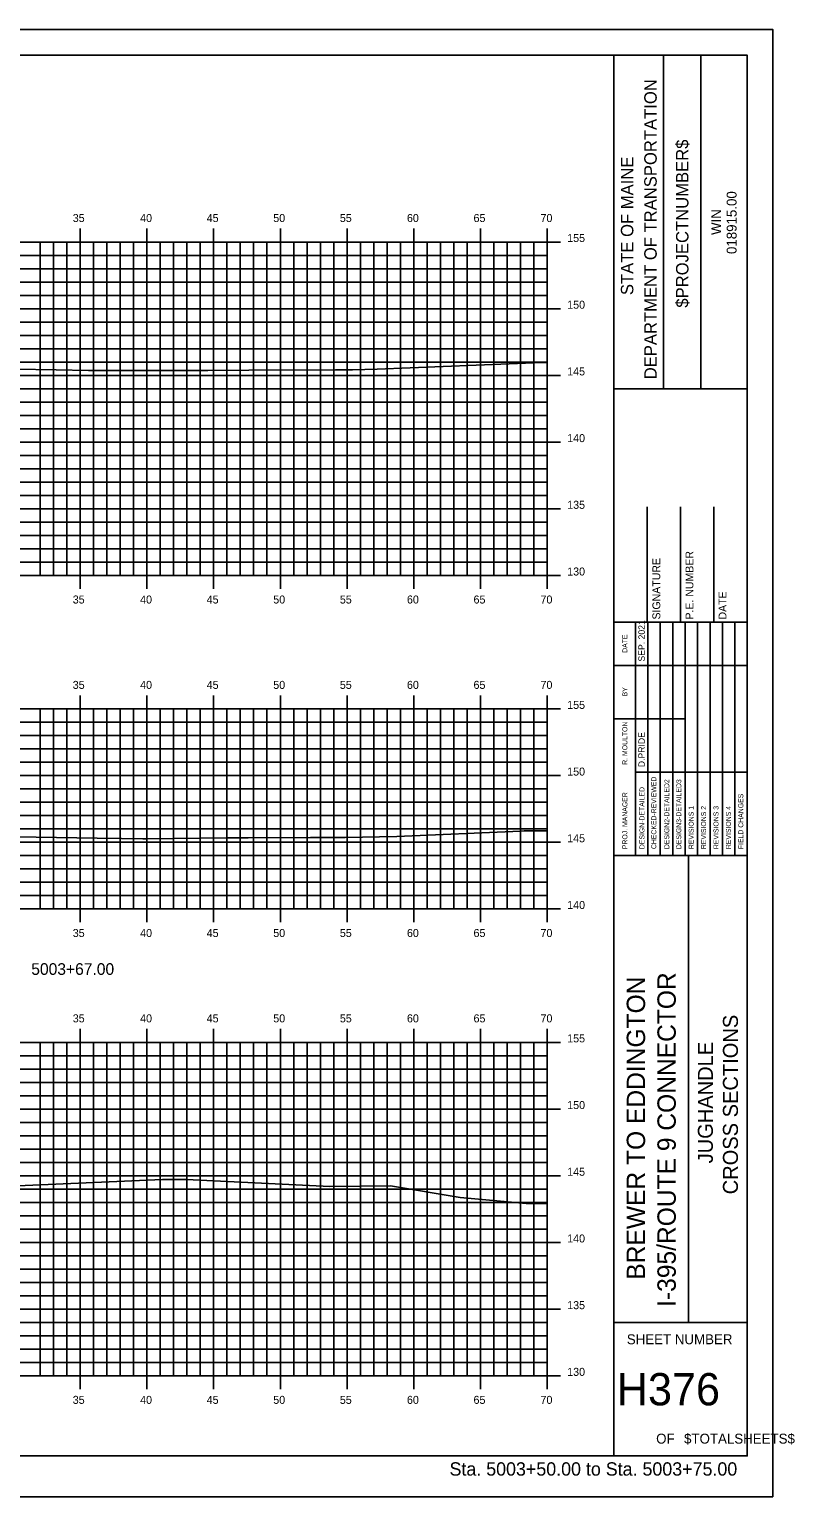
# Model space of a CAD drawing. Extents: x 851860 to 852032, y 365876 to 365986.
# Drawn here: x 851974.6 to 852032, y 365875.8 to 365985.8 of the extents above; entities that cross this region are included whole.
import ezdxf

# ---------------------------------------------------------------- set-up
doc = ezdxf.new("R2010")
doc.units = 0
for name, color, linetype in [('BORDER', 7, 'Continuous'), ('H_V ANNOTATION', 7, 'Continuous'), ('MAJOR', 7, 'Continuous'), ('MINOR', 7, 'Continuous'), ('PLOT BOUNDARY', 7, 'Continuous'), ('S_Roadway_Centerline', 7, 'Continuous')]:
    doc.layers.add(name, color=color, linetype=linetype)

msp = doc.modelspace()

# ---------------------------------------------------------------- linework, layer by layer
at = {"layer": 'BORDER'}
for p, q in [((852018.41, 365878.83), (852018.41, 365983.83)), ((852022.14, 365958.83), (852022.14, 365983.83)), ((852024.94, 365958.83), (852024.94, 365983.83)), ((852018.41, 365958.83), (852028.41, 365958.83)), ((852020.91, 365941.34), (852020.91, 365949.98)), ((852023.41, 365941.34), (852023.41, 365949.98)), ((852025.91, 365941.34), (852025.91, 365949.98)), ((852018.41, 365941.34), (852028.41, 365941.34)), ((852018.41, 365923.84), (852028.41, 365923.84)), ((852024, 365888.84), (852024, 365923.84)), ((852018.41, 365888.84), (852028.41, 365888.84))]:
    msp.add_line(p, q, dxfattribs=at)
msp.add_lwpolyline([(851868.41, 365878.83), (852028.41, 365878.83), (852028.41, 365983.83), (851868.41, 365983.83)], close=True, dxfattribs=at)
for points in [[(852020.03, 365938.09), (852020.03, 365941.34)], [(852020.03, 365923.84), (852020.03, 365940.63)], [(852020.96, 365923.84), (852020.96, 365941.34)], [(852021.89, 365941.34), (852021.89, 365923.84)], [(852022.82, 365923.84), (852022.82, 365941.34)], [(852023.75, 365923.84), (852023.75, 365941.34)], [(852024.69, 365923.84), (852024.69, 365941.34)], [(852025.62, 365923.84), (852025.62, 365941.34)], [(852026.55, 365923.84), (852026.55, 365941.34)], [(852027.48, 365923.84), (852027.48, 365941.34)], [(852018.41, 365938.09), (852028.41, 365938.09)], [(852018.41, 365934.09), (852020.03, 365934.09)], [(852020.03, 365934.09), (852023.75, 365934.09)], [(852020.03, 365930.09), (852028.41, 365930.09)]]:
    msp.add_lwpolyline(points, dxfattribs=at)
at = {"layer": 'MAJOR'}
for p, q in [((851978.41, 365970.84), (851978.41, 365969.83)), ((851983.41, 365970.84), (851983.41, 365969.83)), ((851988.41, 365970.84), (851988.41, 365969.83)), ((851993.41, 365970.84), (851993.41, 365969.83)), ((851998.41, 365970.84), (851998.41, 365969.83)), ((852003.41, 365970.84), (852003.41, 365969.83)), ((852008.41, 365970.84), (852008.41, 365969.83)), ((852013.41, 365970.84), (852013.41, 365969.83)), ((851873.41, 365969.83), (852013.41, 365969.83)), ((851873.41, 365969.83), (852013.41, 365969.83)), ((851978.41, 365944.83), (851978.41, 365969.83)), ((851983.41, 365944.83), (851983.41, 365969.83)), ((851988.41, 365944.83), (851988.41, 365969.83)), ((851993.41, 365944.83), (851993.41, 365969.83)), ((851998.41, 365944.83), (851998.41, 365969.83)), ((852003.41, 365944.83), (852003.41, 365969.83)), ((852008.41, 365944.83), (852008.41, 365969.83)), ((852014.41, 365969.83), (852012.41, 365969.83)), ((852013.41, 365944.83), (852013.41, 365969.83)), ((852013.41, 365944.83), (852013.41, 365969.83)), ((851873.41, 365964.83), (852013.41, 365964.83)), ((852014.41, 365964.83), (852012.41, 365964.83)), ((851873.41, 365959.83), (852013.41, 365959.83)), ((852014.41, 365959.83), (852012.41, 365959.83)), ((851873.41, 365954.83), (852013.41, 365954.83)), ((852014.41, 365954.83), (852012.41, 365954.83)), ((851873.41, 365949.83), (852013.41, 365949.83)), ((852014.41, 365949.83), (852012.41, 365949.83)), ((851873.41, 365944.83), (852013.41, 365944.83)), ((851873.41, 365944.83), (852013.41, 365944.83)), ((851978.41, 365943.83), (851978.41, 365944.83)), ((851983.41, 365943.83), (851983.41, 365944.83)), ((851988.41, 365943.83), (851988.41, 365944.83)), ((851993.41, 365943.83), (851993.41, 365944.83)), ((851998.41, 365943.83), (851998.41, 365944.83)), ((852003.41, 365943.83), (852003.41, 365944.83)), ((852008.41, 365943.83), (852008.41, 365944.83)), ((852014.41, 365944.83), (852012.41, 365944.83)), ((852013.41, 365943.83), (852013.41, 365944.83)), ((851943.41, 365934.83), (852013.41, 365934.83)), ((851943.41, 365934.83), (852013.41, 365934.83)), ((851978.41, 365935.84), (851978.41, 365934.83)), ((851978.41, 365919.83), (851978.41, 365934.83)), ((851983.41, 365935.84), (851983.41, 365934.83)), ((851983.41, 365919.83), (851983.41, 365934.83)), ((851988.41, 365935.84), (851988.41, 365934.83)), ((851988.41, 365919.83), (851988.41, 365934.83)), ((851993.41, 365935.84), (851993.41, 365934.83)), ((851993.41, 365919.83), (851993.41, 365934.83)), ((851998.41, 365935.84), (851998.41, 365934.83)), ((851998.41, 365919.83), (851998.41, 365934.83)), ((852003.41, 365935.84), (852003.41, 365934.83)), ((852003.41, 365919.83), (852003.41, 365934.83)), ((852008.41, 365935.84), (852008.41, 365934.83)), ((852008.41, 365919.83), (852008.41, 365934.83)), ((852014.41, 365934.83), (852012.41, 365934.83)), ((852013.41, 365935.84), (852013.41, 365934.83)), ((852013.41, 365919.83), (852013.41, 365934.83)), ((852013.41, 365919.83), (852013.41, 365934.83)), ((851943.41, 365929.83), (852013.41, 365929.83)), ((852014.41, 365929.83), (852012.41, 365929.83)), ((851943.41, 365924.83), (852013.41, 365924.83)), ((852014.41, 365924.83), (852012.41, 365924.83)), ((851943.41, 365919.83), (852013.41, 365919.83)), ((851943.41, 365919.83), (852013.41, 365919.83)), ((851978.41, 365918.83), (851978.41, 365919.83)), ((851983.41, 365918.83), (851983.41, 365919.83)), ((851988.41, 365918.83), (851988.41, 365919.83)), ((851993.41, 365918.83), (851993.41, 365919.83)), ((851998.41, 365918.83), (851998.41, 365919.83)), ((852003.41, 365918.83), (852003.41, 365919.83)), ((852008.41, 365918.83), (852008.41, 365919.83)), ((852014.41, 365919.83), (852012.41, 365919.83)), ((852013.41, 365918.83), (852013.41, 365919.83)), ((851978.41, 365910.84), (851978.41, 365909.83)), ((851983.41, 365910.84), (851983.41, 365909.83)), ((851988.41, 365910.84), (851988.41, 365909.83)), ((851993.41, 365910.84), (851993.41, 365909.83)), ((851998.41, 365910.84), (851998.41, 365909.83)), ((852003.41, 365910.84), (852003.41, 365909.83)), ((852008.41, 365910.84), (852008.41, 365909.83)), ((852013.41, 365910.84), (852013.41, 365909.83)), ((851873.41, 365909.83), (852013.41, 365909.83)), ((851873.41, 365909.83), (852013.41, 365909.83)), ((851978.41, 365884.83), (851978.41, 365909.83)), ((851983.41, 365884.83), (851983.41, 365909.83)), ((851988.41, 365884.83), (851988.41, 365909.83)), ((851993.41, 365884.83), (851993.41, 365909.83)), ((851998.41, 365884.83), (851998.41, 365909.83)), ((852003.41, 365884.83), (852003.41, 365909.83)), ((852008.41, 365884.83), (852008.41, 365909.83)), ((852014.41, 365909.83), (852012.41, 365909.83)), ((852013.41, 365884.83), (852013.41, 365909.83)), ((852013.41, 365884.83), (852013.41, 365909.83)), ((851873.41, 365904.83), (852013.41, 365904.83)), ((852014.41, 365904.83), (852012.41, 365904.83)), ((851873.41, 365899.83), (852013.41, 365899.83)), ((852014.41, 365899.83), (852012.41, 365899.83)), ((851873.41, 365894.83), (852013.41, 365894.83)), ((852014.41, 365894.83), (852012.41, 365894.83)), ((851873.41, 365889.83), (852013.41, 365889.83)), ((852014.41, 365889.83), (852012.41, 365889.83)), ((851873.41, 365884.83), (852013.41, 365884.83)), ((851873.41, 365884.83), (852013.41, 365884.83)), ((851978.41, 365883.83), (851978.41, 365884.83)), ((851983.41, 365883.83), (851983.41, 365884.83)), ((851988.41, 365883.83), (851988.41, 365884.83)), ((851993.41, 365883.83), (851993.41, 365884.83)), ((851998.41, 365883.83), (851998.41, 365884.83)), ((852003.41, 365883.83), (852003.41, 365884.83)), ((852008.41, 365883.83), (852008.41, 365884.83)), ((852014.41, 365884.83), (852012.41, 365884.83)), ((852013.41, 365883.83), (852013.41, 365884.83))]:
    msp.add_line(p, q, dxfattribs=at)
at = {"layer": 'MINOR'}
for p, q in [((851975.41, 365944.83), (851975.41, 365969.83)), ((851976.41, 365944.83), (851976.41, 365969.83)), ((851977.41, 365944.83), (851977.41, 365969.83)), ((851979.41, 365944.83), (851979.41, 365969.83)), ((851980.41, 365944.83), (851980.41, 365969.83)), ((851981.41, 365944.83), (851981.41, 365969.83)), ((851982.41, 365944.83), (851982.41, 365969.83)), ((851984.41, 365944.83), (851984.41, 365969.83)), ((851985.41, 365944.83), (851985.41, 365969.83)), ((851986.41, 365944.83), (851986.41, 365969.83)), ((851987.41, 365944.83), (851987.41, 365969.83)), ((851989.41, 365944.83), (851989.41, 365969.83)), ((851990.41, 365944.83), (851990.41, 365969.83)), ((851991.41, 365944.83), (851991.41, 365969.83)), ((851992.41, 365944.83), (851992.41, 365969.83)), ((851994.41, 365944.83), (851994.41, 365969.83)), ((851995.41, 365944.83), (851995.41, 365969.83)), ((851996.41, 365944.83), (851996.41, 365969.83)), ((851997.41, 365944.83), (851997.41, 365969.83)), ((851999.41, 365944.83), (851999.41, 365969.83)), ((852000.41, 365944.83), (852000.41, 365969.83)), ((852001.41, 365944.83), (852001.41, 365969.83)), ((852002.41, 365944.83), (852002.41, 365969.83)), ((852004.41, 365944.83), (852004.41, 365969.83)), ((852005.41, 365944.83), (852005.41, 365969.83)), ((852006.41, 365944.83), (852006.41, 365969.83)), ((852007.41, 365944.83), (852007.41, 365969.83)), ((852009.41, 365944.83), (852009.41, 365969.83)), ((852010.41, 365944.83), (852010.41, 365969.83)), ((852011.41, 365944.83), (852011.41, 365969.83)), ((852012.41, 365944.83), (852012.41, 365969.83)), ((851873.41, 365968.83), (852013.41, 365968.83)), ((851873.41, 365967.83), (852013.41, 365967.83)), ((852013.41, 365968.83), (852012.41, 365968.83)), ((852013.41, 365967.83), (852012.41, 365967.83)), ((851873.41, 365966.83), (852013.41, 365966.83)), ((852013.41, 365966.83), (852012.41, 365966.83)), ((851873.41, 365965.83), (852013.41, 365965.83)), ((852013.41, 365965.83), (852012.41, 365965.83)), ((851873.41, 365963.83), (852013.41, 365963.83)), ((852013.41, 365963.83), (852012.41, 365963.83)), ((851873.41, 365962.83), (852013.41, 365962.83)), ((852013.41, 365962.83), (852012.41, 365962.83)), ((851873.41, 365961.83), (852013.41, 365961.83)), ((852013.41, 365961.83), (852012.41, 365961.83)), ((851873.41, 365960.83), (852013.41, 365960.83)), ((852013.41, 365960.83), (852012.41, 365960.83)), ((851873.41, 365958.83), (852013.41, 365958.83)), ((852013.41, 365958.83), (852012.41, 365958.83)), ((851873.41, 365957.83), (852013.41, 365957.83)), ((851873.41, 365956.83), (852013.41, 365956.83)), ((852013.41, 365957.83), (852012.41, 365957.83)), ((852013.41, 365956.83), (852012.41, 365956.83)), ((851873.41, 365955.83), (852013.41, 365955.83)), ((852013.41, 365955.83), (852012.41, 365955.83)), ((851873.41, 365953.83), (852013.41, 365953.83)), ((852013.41, 365953.83), (852012.41, 365953.83)), ((851873.41, 365952.83), (852013.41, 365952.83)), ((852013.41, 365952.83), (852012.41, 365952.83)), ((851873.41, 365951.83), (852013.41, 365951.83)), ((852013.41, 365951.83), (852012.41, 365951.83)), ((851873.41, 365950.83), (852013.41, 365950.83)), ((852013.41, 365950.83), (852012.41, 365950.83)), ((851873.41, 365948.83), (852013.41, 365948.83)), ((852013.41, 365948.83), (852012.41, 365948.83)), ((851873.41, 365947.83), (852013.41, 365947.83)), ((852013.41, 365947.83), (852012.41, 365947.83)), ((851873.41, 365946.83), (852013.41, 365946.83)), ((851873.41, 365945.83), (852013.41, 365945.83)), ((852013.41, 365946.83), (852012.41, 365946.83)), ((852013.41, 365945.83), (852012.41, 365945.83)), ((851975.41, 365919.83), (851975.41, 365934.83)), ((851976.41, 365919.83), (851976.41, 365934.83)), ((851977.41, 365919.83), (851977.41, 365934.83)), ((851979.41, 365919.83), (851979.41, 365934.83)), ((851980.41, 365919.83), (851980.41, 365934.83)), ((851981.41, 365919.83), (851981.41, 365934.83)), ((851982.41, 365919.83), (851982.41, 365934.83)), ((851984.41, 365919.83), (851984.41, 365934.83)), ((851985.41, 365919.83), (851985.41, 365934.83)), ((851986.41, 365919.83), (851986.41, 365934.83)), ((851987.41, 365919.83), (851987.41, 365934.83)), ((851989.41, 365919.83), (851989.41, 365934.83)), ((851990.41, 365919.83), (851990.41, 365934.83)), ((851991.41, 365919.83), (851991.41, 365934.83)), ((851992.41, 365919.83), (851992.41, 365934.83)), ((851994.41, 365919.83), (851994.41, 365934.83)), ((851995.41, 365919.83), (851995.41, 365934.83)), ((851996.41, 365919.83), (851996.41, 365934.83)), ((851997.41, 365919.83), (851997.41, 365934.83)), ((851999.41, 365919.83), (851999.41, 365934.83)), ((852000.41, 365919.83), (852000.41, 365934.83)), ((852001.41, 365919.83), (852001.41, 365934.83)), ((852002.41, 365919.83), (852002.41, 365934.83)), ((852004.41, 365919.83), (852004.41, 365934.83)), ((852005.41, 365919.83), (852005.41, 365934.83)), ((852006.41, 365919.83), (852006.41, 365934.83)), ((852007.41, 365919.83), (852007.41, 365934.83)), ((852009.41, 365919.83), (852009.41, 365934.83)), ((852010.41, 365919.83), (852010.41, 365934.83)), ((852011.41, 365919.83), (852011.41, 365934.83)), ((852012.41, 365919.83), (852012.41, 365934.83)), ((851943.41, 365933.83), (852013.41, 365933.83)), ((852013.41, 365933.83), (852012.41, 365933.83)), ((851943.41, 365932.83), (852013.41, 365932.83)), ((852013.41, 365932.83), (852012.41, 365932.83)), ((851943.41, 365931.83), (852013.41, 365931.83)), ((852013.41, 365931.83), (852012.41, 365931.83)), ((851943.41, 365930.83), (852013.41, 365930.83)), ((852013.41, 365930.83), (852012.41, 365930.83)), ((851943.41, 365928.83), (852013.41, 365928.83)), ((852013.41, 365928.83), (852012.41, 365928.83)), ((851943.41, 365927.83), (852013.41, 365927.83)), ((852013.41, 365927.83), (852012.41, 365927.83)), ((851943.41, 365926.83), (852013.41, 365926.83)), ((852013.41, 365926.83), (852012.41, 365926.83)), ((851943.41, 365925.83), (852013.41, 365925.83)), ((852013.41, 365925.83), (852012.41, 365925.83)), ((851943.41, 365923.83), (852013.41, 365923.83)), ((852013.41, 365923.83), (852012.41, 365923.83)), ((851943.41, 365922.83), (852013.41, 365922.83)), ((852013.41, 365922.83), (852012.41, 365922.83)), ((851943.41, 365921.83), (852013.41, 365921.83)), ((852013.41, 365921.83), (852012.41, 365921.83)), ((851943.41, 365920.83), (852013.41, 365920.83)), ((852013.41, 365920.83), (852012.41, 365920.83)), ((851975.41, 365884.83), (851975.41, 365909.83)), ((851976.41, 365884.83), (851976.41, 365909.83)), ((851977.41, 365884.83), (851977.41, 365909.83)), ((851979.41, 365884.83), (851979.41, 365909.83)), ((851980.41, 365884.83), (851980.41, 365909.83)), ((851981.41, 365884.83), (851981.41, 365909.83)), ((851982.41, 365884.83), (851982.41, 365909.83)), ((851984.41, 365884.83), (851984.41, 365909.83)), ((851985.41, 365884.83), (851985.41, 365909.83)), ((851986.41, 365884.83), (851986.41, 365909.83)), ((851987.41, 365884.83), (851987.41, 365909.83)), ((851989.41, 365884.83), (851989.41, 365909.83)), ((851990.41, 365884.83), (851990.41, 365909.83)), ((851991.41, 365884.83), (851991.41, 365909.83)), ((851992.41, 365884.83), (851992.41, 365909.83)), ((851994.41, 365884.83), (851994.41, 365909.83)), ((851995.41, 365884.83), (851995.41, 365909.83)), ((851996.41, 365884.83), (851996.41, 365909.83)), ((851997.41, 365884.83), (851997.41, 365909.83)), ((851999.41, 365884.83), (851999.41, 365909.83)), ((852000.41, 365884.83), (852000.41, 365909.83)), ((852001.41, 365884.83), (852001.41, 365909.83)), ((852002.41, 365884.83), (852002.41, 365909.83)), ((852004.41, 365884.83), (852004.41, 365909.83)), ((852005.41, 365884.83), (852005.41, 365909.83)), ((852006.41, 365884.83), (852006.41, 365909.83)), ((852007.41, 365884.83), (852007.41, 365909.83)), ((852009.41, 365884.83), (852009.41, 365909.83)), ((852010.41, 365884.83), (852010.41, 365909.83)), ((852011.41, 365884.83), (852011.41, 365909.83)), ((852012.41, 365884.83), (852012.41, 365909.83)), ((851873.41, 365908.83), (852013.41, 365908.83)), ((852013.41, 365908.83), (852012.41, 365908.83)), ((851873.41, 365907.83), (852013.41, 365907.83)), ((852013.41, 365907.83), (852012.41, 365907.83)), ((851873.41, 365906.83), (852013.41, 365906.83)), ((852013.41, 365906.83), (852012.41, 365906.83)), ((851873.41, 365905.83), (852013.41, 365905.83)), ((852013.41, 365905.83), (852012.41, 365905.83)), ((851873.41, 365903.83), (852013.41, 365903.83)), ((852013.41, 365903.83), (852012.41, 365903.83)), ((851873.41, 365902.83), (852013.41, 365902.83)), ((851873.41, 365901.83), (852013.41, 365901.83)), ((852013.41, 365902.83), (852012.41, 365902.83)), ((852013.41, 365901.83), (852012.41, 365901.83)), ((851873.41, 365900.83), (852013.41, 365900.83)), ((852013.41, 365900.83), (852012.41, 365900.83)), ((851873.41, 365898.83), (852013.41, 365898.83)), ((852013.41, 365898.83), (852012.41, 365898.83)), ((851873.41, 365897.83), (852013.41, 365897.83)), ((852013.41, 365897.83), (852012.41, 365897.83)), ((851873.41, 365896.83), (852013.41, 365896.83)), ((852013.41, 365896.83), (852012.41, 365896.83)), ((851873.41, 365895.83), (852013.41, 365895.83)), ((852013.41, 365895.83), (852012.41, 365895.83)), ((851873.41, 365893.83), (852013.41, 365893.83)), ((852013.41, 365893.83), (852012.41, 365893.83)), ((851873.41, 365892.83), (852013.41, 365892.83)), ((852013.41, 365892.83), (852012.41, 365892.83)), ((851873.41, 365891.83), (852013.41, 365891.83)), ((851873.41, 365890.83), (852013.41, 365890.83)), ((852013.41, 365891.83), (852012.41, 365891.83)), ((852013.41, 365890.83), (852012.41, 365890.83)), ((851873.41, 365888.83), (852013.41, 365888.83)), ((852013.41, 365888.83), (852012.41, 365888.83)), ((851873.41, 365887.83), (852013.41, 365887.83)), ((852013.41, 365887.83), (852012.41, 365887.83)), ((851873.41, 365886.83), (852013.41, 365886.83)), ((852013.41, 365886.83), (852012.41, 365886.83)), ((851873.41, 365885.83), (852013.41, 365885.83)), ((852013.41, 365885.83), (852012.41, 365885.83))]:
    msp.add_line(p, q, dxfattribs=at)
at = {"layer": 'PLOT BOUNDARY'}
msp.add_lwpolyline([(851860.32, 365875.77), (852030.32, 365875.77), (852030.32, 365985.77), (851860.32, 365985.77)], close=True, dxfattribs=at)
at = {"layer": 'S_Roadway_Centerline'}
for points in [[(851973.54, 365960.31), (851976.61, 365960.25), (851979.02, 365960.21), (851981.6, 365960.21), (851983.59, 365960.2), (851983.89, 365960.2), (851986.36, 365960.19), (851987.98, 365960.21), (851991.04, 365960.23), (851997.55, 365960.24), (851998.82, 365960.24), (852000.67, 365960.31), (852013.03, 365960.79), (852013.41, 365960.81)], [(851970.5, 365925.3), (851979.67, 365925.14), (851981.51, 365925.11), (851983.11, 365925.08), (851983.34, 365925.08), (851983.44, 365925.08), (851989.35, 365925.16), (851991, 365925.17), (851995.68, 365925.18), (851998.28, 365925.18), (852002.13, 365925.27), (852011.42, 365925.67), (852011.69, 365925.68), (852011.89, 365925.69), (852013.41, 365925.7)], [(851917.31, 365892.54), (851920.06, 365892.8), (851924.76, 365892.75), (851934.09, 365894.97), (851936.02, 365895.39), (851941.54, 365895.94), (851946.04, 365896.13), (851951.08, 365897.16), (851957.77, 365897.9), (851964.53, 365898.67), (851984.58, 365899.54), (851985.27, 365899.55), (851985.44, 365899.55), (851985.6, 365899.55), (851986.37, 365899.54), (851997.13, 365899.02), (852001.67, 365899.08), (852006.9, 365898.21), (852011.84, 365897.76), (852013.41, 365897.72)]]:
    msp.add_lwpolyline(points, dxfattribs=at)

# ---------------------------------------------------------------- texts
at = {"layer": 'BORDER'}
for s, height, p in [('DEPARTMENT OF TRANSPORTATION', 0.9318, (852021.62, 365959.54)), ('$PROJECTNUMBER$', 0.9318, (852024, 365964.91)), ('STATE OF MAINE', 0.9318, (852019.87, 365965.85)), ('018915.00', 0.745, (852027.61, 365968.93)), ('WIN', 0.745, (852026.45, 365970.36)), ('SIGNATURE', 0.591, (852021.89, 365941.53)), ('P.E. NUMBER', 0.5906, (852024.37, 365941.53)), ('DATE', 0.591, (852026.85, 365941.53)), ('SEP. 2021', 0.485, (852020.73, 365938.38)), ('DATE', 0.371, (852019.42, 365939.04)), ('BY', 0.371, (852019.42, 365935.77)), ('R. MOULTON', 0.373, (852019.42, 365930.64)), ('D.PRIDE', 0.485, (852020.73, 365930.46)), ('CHECKED-REVIEWED', 0.3727, (852021.59, 365924.32)), ('DESIGN2-DETAILED2', 0.3727, (852022.56, 365924.32)), ('DESIGN3-DETAILED3', 0.3727, (852023.46, 365924.32)), ('PROJ. MANAGER', 0.3727, (852019.42, 365924.32)), ('DESIGN-DETAILED', 0.3727, (852020.7, 365924.32)), ('FIELD CHANGES', 0.3727, (852028.11, 365924.32)), ('REVISIONS 1', 0.3727, (852024.39, 365924.32)), ('REVISIONS 2', 0.3727, (852025.32, 365924.32)), ('REVISIONS 3', 0.3727, (852026.25, 365924.32)), ('REVISIONS 4', 0.3727, (852027.18, 365924.32)), ('BREWER TO EDDINGTON', 1.3779, (852020.75, 365892.04)), ('I-395/ROUTE 9 CONNECTOR', 1.3779, (852023.05, 365890)), ('CROSS SECTIONS', 1.125, (852027.71, 365898.44)), ('JUGHANDLE', 1.125, (852025.83, 365900.76))]:
    msp.add_text(s, height=height, rotation=90, dxfattribs=at).set_placement(p)
for s, height, p in [('SHEET NUMBER', 0.7453, (852019.38, 365887.2)), ('H376', 2.419, (852018.63, 365882.62)), ('OF', 0.745, (852021.58, 365879.75)), ('$TOTALSHEETS$', 0.7453, (852023.67, 365879.75))]:
    msp.add_text(s, height=height, dxfattribs=at).set_placement(p)
at = {"layer": 'H_V ANNOTATION'}
for s, height, p in [('35', 0.6, (851977.85, 365971.33)), ('40', 0.6, (851982.9, 365971.33)), ('45', 0.6, (851987.89, 365971.33)), ('50', 0.6, (851992.88, 365971.33)), ('55', 0.6, (851997.87, 365971.33)), ('60', 0.6, (852002.9, 365971.33)), ('65', 0.6, (852007.89, 365971.33)), ('70', 0.6, (852012.91, 365971.33)), ('155', 0.6, (852014.91, 365969.83)), ('150', 0.6, (852014.91, 365964.83)), ('145', 0.6, (852014.91, 365959.83)), ('140', 0.6, (852014.91, 365954.83)), ('135', 0.6, (852014.91, 365949.83)), ('130', 0.6, (852014.91, 365944.83)), ('35', 0.6, (851977.85, 365942.73)), ('40', 0.6, (851982.9, 365942.73)), ('45', 0.6, (851987.89, 365942.73)), ('50', 0.6, (851992.88, 365942.73)), ('55', 0.6, (851997.87, 365942.73)), ('60', 0.6, (852002.9, 365942.73)), ('65', 0.6, (852007.89, 365942.73)), ('70', 0.6, (852012.91, 365942.73)), ('35', 0.6, (851977.85, 365936.33)), ('40', 0.6, (851982.9, 365936.33)), ('45', 0.6, (851987.89, 365936.33)), ('50', 0.6, (851992.88, 365936.33)), ('55', 0.6, (851997.87, 365936.33)), ('60', 0.6, (852002.9, 365936.33)), ('65', 0.6, (852007.89, 365936.33)), ('70', 0.6, (852012.91, 365936.33)), ('155', 0.6, (852014.91, 365934.83)), ('150', 0.6, (852014.91, 365929.83)), ('145', 0.6, (852014.91, 365924.83)), ('140', 0.6, (852014.91, 365919.83)), ('35', 0.6, (851977.85, 365917.73)), ('40', 0.6, (851982.9, 365917.73)), ('45', 0.6, (851987.89, 365917.73)), ('50', 0.6, (851992.88, 365917.73)), ('55', 0.6, (851997.87, 365917.73)), ('60', 0.6, (852002.9, 365917.73)), ('65', 0.6, (852007.89, 365917.73)), ('70', 0.6, (852012.91, 365917.73)), ('5003+67.00', 0.875, (851974.74, 365914.89)), ('35', 0.6, (851977.85, 365911.33)), ('40', 0.6, (851982.9, 365911.33)), ('45', 0.6, (851987.89, 365911.33)), ('50', 0.6, (851992.88, 365911.33)), ('55', 0.6, (851997.87, 365911.33)), ('60', 0.6, (852002.9, 365911.33)), ('65', 0.6, (852007.89, 365911.33)), ('70', 0.6, (852012.91, 365911.33)), ('155', 0.6, (852014.91, 365909.83)), ('150', 0.6, (852014.91, 365904.83)), ('145', 0.6, (852014.91, 365899.83)), ('140', 0.6, (852014.91, 365894.83)), ('135', 0.6, (852014.91, 365889.83)), ('130', 0.6, (852014.91, 365884.83)), ('35', 0.6, (851977.85, 365882.73)), ('40', 0.6, (851982.9, 365882.73)), ('45', 0.6, (851987.89, 365882.73)), ('50', 0.6, (851992.88, 365882.73)), ('55', 0.6, (851997.87, 365882.73)), ('60', 0.6, (852002.9, 365882.73)), ('65', 0.6, (852007.89, 365882.73)), ('70', 0.6, (852012.91, 365882.73)), ('Sta. 5003+50.00 to Sta. 5003+75.00', 1.0002, (852006.09, 365877.35))]:
    msp.add_text(s, height=height, dxfattribs=at).set_placement(p)

doc.saveas('drawing.dxf')
